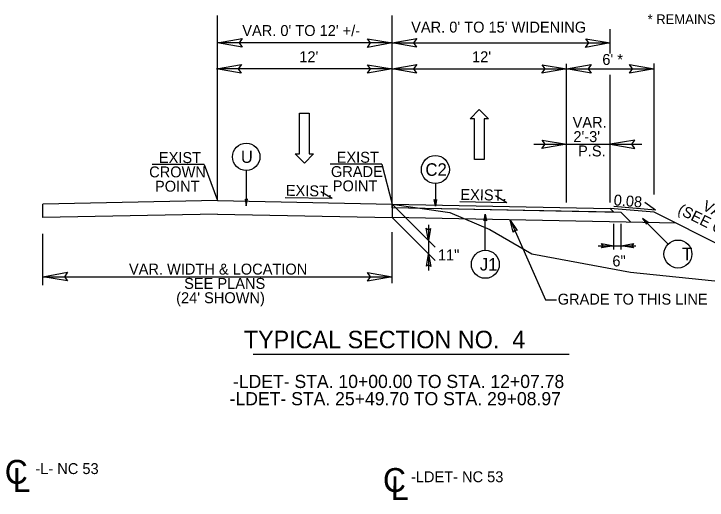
# Model space of a CAD drawing. Extents: x 1548135 to 1549339, y 868664 to 869085.
# Drawn here: x 1548194.74 to 1548242.4, y 868835.58 to 868868.97 of the extents above; entities that cross this region are included whole.
import ezdxf

# ---------------------------------------------------------------- set-up
doc = ezdxf.new("R2010")
doc.units = 0
for name, color, linetype in [('P_RDY_TC_Pvmt_Asphalt_Base_Course', 7, 'Continuous'), ('Prop Dimension', 7, 'Continuous'), ('Prop Terminator CELL', 7, 'Continuous'), ('Sheet_Data_Field_CELL', 7, 'Continuous'), ('Sheet_Plan', 7, 'Continuous'), ('Sheet_Title_Block_Text', 7, 'Continuous'), ('Typical Grade Point Symbol CELL', 7, 'Continuous'), ('Typical Hinge Slope Arterial CELL', 7, 'Continuous'), ('Typical Hinge Slope Interstate CELL', 7, 'Continuous'), ('Typical Pavement Slope Information CELL', 7, 'Continuous'), ('Typical Shoulder Slope CELL', 7, 'Continuous'), ('Typical Shoulder Slope Information CELL', 7, 'Continuous'), ('Typical Terminator CELL', 7, 'Continuous'), ('Typical Text Centerline CELL', 7, 'Continuous'), ('Typical Text General CELL', 7, 'Continuous'), ('Typical Text Grade Point CELL', 7, 'Continuous'), ('z - Construction', 7, 'Continuous')]:
    doc.layers.add(name, color=color, linetype=linetype)

msp = doc.modelspace()

# ---------------------------------------------------------------- linework, layer by layer
at = {"layer": 'P_RDY_TC_Pvmt_Asphalt_Base_Course'}
for points in [[(1548210.425, 868866.683), (1548208.737, 868866.973), (1548210.434, 868867.273), (1548210.218, 868866.973)], [(1548219.05, 868867.264), (1548220.737, 868866.973), (1548219.04, 868866.673), (1548219.256, 868866.973)], [(1548222.425, 868866.683), (1548220.737, 868866.973), (1548222.434, 868867.273), (1548222.218, 868866.973)], [(1548234.05, 868867.264), (1548235.737, 868866.973), (1548234.04, 868866.673), (1548234.256, 868866.973)], [(1548210.365, 868864.9), (1548208.678, 868865.191), (1548210.375, 868865.491), (1548210.159, 868865.191)], [(1548219.05, 868865.481), (1548220.737, 868865.191), (1548219.04, 868864.891), (1548219.256, 868865.191)], [(1548222.425, 868864.9), (1548220.737, 868865.191), (1548222.434, 868865.491), (1548222.218, 868865.191)], [(1548231.05, 868865.481), (1548232.737, 868865.191), (1548231.04, 868864.891), (1548231.256, 868865.191)], [(1548234.425, 868864.9), (1548232.737, 868865.191), (1548234.434, 868865.491), (1548234.218, 868865.191)], [(1548237.061, 868865.499), (1548238.748, 868865.208), (1548237.052, 868864.908), (1548237.267, 868865.208)], [(1548231.05, 868860.308), (1548232.737, 868860.018), (1548231.04, 868859.718), (1548231.256, 868860.018)], [(1548237.425, 868860.308), (1548235.737, 868860.018), (1548237.434, 868859.718), (1548237.219, 868860.018)], [(1548198.425, 868850.632), (1548196.737, 868850.923), (1548198.434, 868851.223), (1548198.218, 868850.923)], [(1548219.05, 868851.214), (1548220.737, 868850.923), (1548219.04, 868850.623), (1548219.256, 868850.923)]]:
    msp.add_lwpolyline(points, close=True, dxfattribs=at)
at = {"layer": 'Prop Dimension'}
msp.add_line((1548249.386, 868850.034), (1548238.748, 868855.353), dxfattribs=at)
at = {"layer": 'Prop Terminator CELL'}
msp.add_lwpolyline([(1548220.737, 868855.904), (1548235.737, 868855.604), (1548235.988, 868855.349), (1548231.175, 868855.445), (1548229.866, 868855.472), (1548227.571, 868855.518), (1548220.737, 868855.654), (1548220.737, 868855.654)], close=True, dxfattribs=at)
at = {"layer": 'Sheet_Plan'}
msp.add_line((1548238.748, 868855.353), (1548235.737, 868855.604), dxfattribs=at)
at = {"layer": 'Typical Grade Point Symbol CELL'}
for p, q in [((1548208.737, 868856.184), (1548208.737, 868868.855)), ((1548220.737, 868855.904), (1548220.737, 868868.855)), ((1548235.737, 868866.25), (1548235.737, 868867.926)), ((1548220.737, 868866.973), (1548208.737, 868866.973)), ((1548220.737, 868866.973), (1548235.737, 868866.973)), ((1548232.737, 868856.024), (1548232.737, 868865.536)), ((1548238.748, 868856.57), (1548238.748, 868865.554)), ((1548220.737, 868865.191), (1548208.737, 868865.191)), ((1548220.737, 868865.191), (1548238.748, 868865.191)), ((1548235.737, 868856.024), (1548235.737, 868864.785)), ((1548230.487, 868860.018), (1548237.918, 868860.018))]:
    msp.add_line(p, q, dxfattribs=at)
at = {"layer": 'Typical Hinge Slope Arterial CELL'}
for p, q in [((1548207.813, 868858.631), (1548204.256, 868858.631)), ((1548220.035, 868858.652), (1548216.478, 868858.652))]:
    msp.add_line(p, q, dxfattribs=at)
at = {"layer": 'Typical Hinge Slope Interstate CELL'}
for p, q in [((1548210.714, 868858.216), (1548210.714, 868855.781)), ((1548223.714, 868857.32), (1548223.714, 868855.758)), ((1548208.737, 868856.144), (1548196.737, 868855.904)), ((1548196.737, 868854.988), (1548196.737, 868855.904)), ((1548208.737, 868856.144), (1548220.737, 868855.904)), ((1548223.689, 868852.953), (1548220.737, 868855.904)), ((1548220.737, 868855.904), (1548220.737, 868854.988)), ((1548208.737, 868855.228), (1548196.737, 868854.988)), ((1548208.737, 868855.228), (1548220.737, 868854.988)), ((1548236.488, 868855.339), (1548220.737, 868855.654)), ((1548227.149, 868852.737), (1548227.149, 868855.222)), ((1548223.689, 868852.036), (1548220.737, 868854.988)), ((1548240.261, 868854.597), (1548220.737, 868854.988)), ((1548239.712, 868853.159), (1548237.954, 868854.917)), ((1548223.242, 868854.478), (1548223.244, 868851.346)), ((1548235.988, 868852.793), (1548235.988, 868854.543)), ((1548236.488, 868852.793), (1548236.488, 868854.543)), ((1548234.91, 868853.048), (1548237.499, 868853.05))]:
    msp.add_line(p, q, dxfattribs=at)
for points in [[(1548210.635, 868856.24), (1548210.714, 868855.781), (1548210.796, 868856.242), (1548210.714, 868856.184)], [(1548223.794, 868856.227), (1548223.714, 868855.758), (1548223.63, 868856.229), (1548223.714, 868856.169)], [(1548227.069, 868854.753), (1548227.149, 868855.222), (1548227.233, 868854.751), (1548227.149, 868854.811)], [(1548229.072, 868853.97), (1548228.862, 868854.8), (1548229.343, 868854.085), (1548229.163, 868854.123)], [(1548238.342, 868854.642), (1548237.954, 868854.917), (1548238.228, 868854.524), (1548238.245, 868854.626)], [(1548223.387, 868854.243), (1548223.242, 868853.399), (1548223.092, 868854.248), (1548223.242, 868854.14)], [(1548235.144, 868853.194), (1548235.988, 868853.049), (1548235.14, 868852.899), (1548235.248, 868853.049)], [(1548237.332, 868852.904), (1548236.488, 868853.049), (1548237.337, 868853.199), (1548237.229, 868853.049)], [(1548223.098, 868851.638), (1548223.243, 868852.481), (1548223.393, 868851.633), (1548223.243, 868851.741)]]:
    msp.add_lwpolyline(points, close=True, dxfattribs=at)
for points in [[(1548220.737, 868855.904), (1548224.718, 868855.321), (1548227.45, 868854.175), (1548230.353, 868852.494), (1548237.134, 868851.24), (1548249.386, 868849.971)], [(1548228.851, 868854.825), (1548231.287, 868849.335), (1548232.038, 868849.335)]]:
    msp.add_lwpolyline(points, dxfattribs=at)
for centre, radius in [((1548210.714, 868859.158), 0.942), ((1548223.714, 868858.282), 0.962), ((1548240.391, 868852.479), 0.962), ((1548227.149, 868851.775), 0.962)]:
    msp.add_circle(centre, radius, dxfattribs=at)
at = {"layer": 'Typical Pavement Slope Information CELL'}
for p, q in [((1548216.62, 868856.283), (1548215.837, 868856.757)), ((1548216.62, 868856.283), (1548213.39, 868856.348)), ((1548228.62, 868856.003), (1548227.837, 868856.477)), ((1548228.62, 868856.003), (1548225.39, 868856.068)), ((1548238.859, 868855.493), (1548235.976, 868855.733)), ((1548238.859, 868855.493), (1548238.108, 868856.015))]:
    msp.add_line(p, q, dxfattribs=at)
at = {"layer": 'Typical Shoulder Slope CELL'}
for p, q in [((1548207.813, 868858.631), (1548208.737, 868856.144)), ((1548220.035, 868858.652), (1548220.737, 868855.904))]:
    msp.add_line(p, q, dxfattribs=at)
at = {"layer": 'Typical Shoulder Slope Information CELL'}
for p, q in [((1548226.101, 868861.774), (1548226.721, 868862.404)), ((1548226.721, 868862.404), (1548227.361, 868861.774)), ((1548214.384, 868859.36), (1548214.384, 868862.16)), ((1548214.384, 868862.16), (1548215.044, 868862.16)), ((1548215.044, 868862.16), (1548215.044, 868859.36)), ((1548226.401, 868861.774), (1548226.101, 868861.774)), ((1548226.401, 868858.974), (1548226.401, 868861.774)), ((1548227.361, 868861.774), (1548227.061, 868861.774)), ((1548227.061, 868861.774), (1548227.061, 868858.974)), ((1548214.724, 868858.73), (1548214.084, 868859.36)), ((1548214.084, 868859.36), (1548214.384, 868859.36)), ((1548215.344, 868859.36), (1548214.724, 868858.73)), ((1548215.044, 868859.36), (1548215.344, 868859.36)), ((1548227.061, 868858.974), (1548226.401, 868858.974))]:
    msp.add_line(p, q, dxfattribs=at)
at = {"layer": 'Typical Terminator CELL'}
for p, q in [((1548196.737, 868850.352), (1548196.737, 868853.856)), ((1548220.737, 868850.468), (1548220.737, 868853.971)), ((1548196.737, 868850.923), (1548220.737, 868850.923)), ((1548211.185, 868845.607), (1548232.906, 868845.607))]:
    msp.add_line(p, q, dxfattribs=at)
at = {"layer": 'Typical Text Grade Point CELL'}
for p, q in [((1548220.737, 868855.904), (1548235.737, 868855.604)), ((1548235.737, 868855.604), (1548235.988, 868855.349)), ((1548236.488, 868855.339), (1548237.155, 868854.659))]:
    msp.add_line(p, q, dxfattribs=at)

# ---------------------------------------------------------------- texts
at = {"layer": 'Sheet_Data_Field_CELL'}
for s, p in [('VAR. 1.5:1 TO 3:1', (1548242.016, 868855.538)), ('(SEE CROSS SECTIONS)', (1548240.316, 868855.289))]:
    msp.add_text(s, height=0.75, rotation=333.434, dxfattribs=at).set_placement(p)
at = {"layer": 'Sheet_Title_Block_Text'}
for p in [(1548194.11, 868836.699), (1548220.11, 868836.139)]:
    msp.add_text('C', height=1.64, dxfattribs=at).set_placement(p)
for p in [(1548194.655, 868836.139), (1548220.655, 868835.579)]:
    msp.add_text('L', height=1.641, rotation=359.9469, dxfattribs=at).set_placement(p)
at = {"layer": 'Typical Hinge Slope Arterial CELL'}
msp.add_text('  TYPICAL SECTION NO.  4', height=1.2, dxfattribs=at).set_placement((1548209.655, 868846.009))
at = {"layer": 'Typical Hinge Slope Interstate CELL'}
for s, height, p in [('U', 0.844, (1548210.346, 868858.737)), ('C2', 0.8608, (1548223.028, 868857.851)), ('T', 0.861, (1548240.674, 868852.049)), ('11"', 0.75, (1548223.889, 868852.041)), ('6"', 0.75, (1548235.884, 868851.629)), ('J1', 0.8608, (1548226.771, 868851.345)), ('GRADE TO THIS LINE', 0.75, (1548232.125, 868849.005)), ('-L- NC 53', 0.75, (1548196.218, 868837.366)), ('-LDET- NC 53', 0.75, (1548222.037, 868836.806))]:
    msp.add_text(s, height=height, dxfattribs=at).set_placement(p)
at = {"layer": 'Typical Pavement Slope Information CELL'}
for p in [(1548213.427, 868856.482), (1548225.427, 868856.202)]:
    msp.add_text('EXIST.', height=0.75, rotation=358.8544, dxfattribs=at).set_placement(p)
at = {"layer": 'Typical Shoulder Slope CELL'}
for s, p in [("VAR. 0' TO 12' +/-", (1548210.439, 868867.452)), ("VAR. 0' TO 15' WIDENING", (1548222.05, 868867.688)), ("12'", (1548214.36, 868865.651)), ("12'", (1548226.237, 868865.651)), ("6' *", (1548235.192, 868865.466)), ('EXIST', (1548216.93, 868858.75)), ('EXIST', (1548204.708, 868858.728)), ('CROWN', (1548204.039, 868857.745)), ('GRADE', (1548216.534, 868857.767)), ('POINT', (1548204.439, 868856.762)), ('POINT', (1548216.66, 868856.783)), ('VAR. WIDTH & LOCATION', (1548202.649, 868851.069)), ('SEE PLANS', (1548206.445, 868850.086)), ("(24' SHOWN)", (1548205.895, 868849.103))]:
    msp.add_text(s, height=0.75, dxfattribs=at).set_placement(p)
at = {"layer": 'Typical Text Centerline CELL'}
for s, p in [('VAR. ', (1548233.151, 868861.15)), ("2'-3'", (1548233.202, 868860.167)), ('P.S.', (1548233.523, 868859.184))]:
    msp.add_text(s, height=0.75, dxfattribs=at).set_placement(p)
at = {"layer": 'Typical Text General CELL'}
for s, height, p in [("* REMAINS 6' W/ GUARDRAIL", 0.66824, (1548238.304, 868868.268)), ('-LDET- STA. 10+00.00 TO STA. 12+07.78', 0.90387, (1548209.798, 868843.277)), ('-LDET- STA. 25+49.70 TO STA. 29+08.97', 0.90387, (1548209.57, 868842.092))]:
    msp.add_text(s, height=height, dxfattribs=at).set_placement(p)
at = {"layer": 'z - Construction'}
msp.add_text('0.08', height=0.75, rotation=355.2385, dxfattribs=at).set_placement((1548235.952, 868855.831))

doc.saveas('drawing.dxf')
